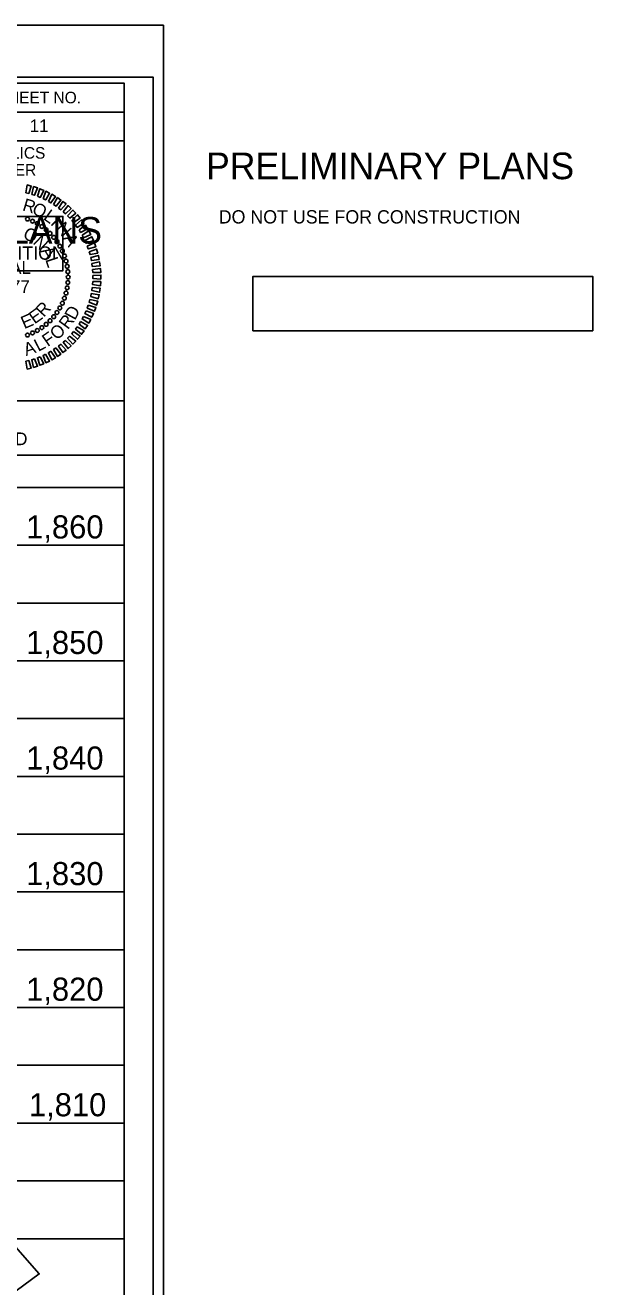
# Model space of a CAD drawing. Extents: x 557032 to 562069, y 513430 to 515874.
# Drawn here: x 558657 to 558902, y 515328 to 515874 of the extents above; entities that cross this region are included whole.
import ezdxf

# ---------------------------------------------------------------- set-up
doc = ezdxf.new("R2010")
doc.units = 0
for name, color, linetype in [('Default', 7, 'Continuous'), ('Exist Vertical Profile Vertical Axis Label', 7, 'Continuous'), ('Scratch_Level_5', 7, 'Continuous'), ('Sheet Cutting Line CELL', 7, 'Continuous'), ('Sheet Data Field CELL', 7, 'Continuous'), ('Sheet DOT Grid CELL', 7, 'Continuous'), ('Sheet Plot Border Inside CELL', 7, 'Continuous'), ('Sheet Plot Border Outside CELL', 7, 'Continuous'), ('Sheet Profile CELL', 7, 'Continuous'), ('Sheet Profile Grid Major CELL', 7, 'Continuous'), ('Sheet Profile Grid Middle CELL', 7, 'Continuous'), ('Sheet Sticker Exception Certification CELL', 7, 'Continuous'), ('Sheet Sticker Incomplete CELL', 7, 'Continuous'), ('Sheet Sticker Preliminary CELL', 7, 'Continuous')]:
    doc.layers.add(name, color=color, linetype=linetype)

msp = doc.modelspace()

# ---------------------------------------------------------------- linework, layer by layer
at = {"layer": 'Default'}
for points in [[(558656.99, 515801.79), (558657.57, 515805.17), (558659.28, 515804.71), (558658.21, 515801.49)], [(558659.51, 515801.11), (558660.32, 515804.45), (558662, 515803.87), (558660.71, 515800.73)], [(558661.98, 515800.26), (558663.02, 515803.53), (558664.66, 515802.83), (558663.15, 515799.79)], [(558664.38, 515799.23), (558665.65, 515802.43), (558667.24, 515801.62), (558665.52, 515798.69)], [(558666.71, 515798.05), (558668.2, 515801.14), (558669.72, 515800.23), (558667.8, 515797.42)], [(558668.95, 515796.7), (558670.65, 515799.68), (558672.1, 515798.66), (558669.99, 515796)], [(558671.09, 515795.2), (558672.99, 515798.06), (558674.37, 515796.94), (558672.08, 515794.43)], [(558673.11, 515793.55), (558675.21, 515796.27), (558676.51, 515795.06), (558674.05, 515792.72)], [(558675.02, 515791.77), (558677.31, 515794.34), (558678.52, 515793.04), (558675.9, 515790.87)], [(558676.8, 515789.86), (558679.26, 515792.26), (558680.38, 515790.88), (558677.62, 515788.9)], [(558678.44, 515787.83), (558681.06, 515790.05), (558682.08, 515788.59), (558679.19, 515786.82)], [(558679.94, 515785.69), (558682.71, 515787.72), (558683.62, 515786.2), (558680.61, 515784.62)], [(558681.28, 515783.45), (558684.19, 515785.29), (558684.99, 515783.7), (558681.88, 515782.34)], [(558682.47, 515781.12), (558685.49, 515782.75), (558686.18, 515781.11), (558682.99, 515779.97)], [(558683.49, 515778.71), (558686.62, 515780.13), (558687.19, 515778.45), (558683.92, 515777.53)], [(558684.33, 515776.24), (558687.55, 515777.44), (558688.01, 515775.72), (558684.69, 515775.04)], [(558685.01, 515773.72), (558688.3, 515774.69), (558688.64, 515772.94), (558685.28, 515772.49)], [(558685.5, 515771.16), (558688.86, 515771.89), (558689.08, 515770.12), (558685.69, 515769.91)], [(558685.82, 515768.56), (558689.22, 515769.06), (558689.31, 515767.28), (558685.91, 515767.31)], [(558685.91, 515763.34), (558689.34, 515763.36), (558689.19, 515761.59), (558685.83, 515762.09)], [(558685.95, 515765.95), (558689.38, 515766.21), (558689.35, 515764.44), (558685.96, 515764.7)], [(558685.26, 515758.16), (558688.67, 515757.7), (558688.27, 515755.97), (558685.01, 515756.93)], [(558685.68, 515760.74), (558689.1, 515760.52), (558688.82, 515758.77), (558685.51, 515759.5)], [(558683.91, 515753.12), (558687.22, 515752.19), (558686.58, 515750.53), (558683.49, 515751.94)], [(558684.68, 515755.62), (558688.04, 515754.92), (558687.52, 515753.22), (558684.34, 515754.41)], [(558681.87, 515748.32), (558685.01, 515746.94), (558684.15, 515745.38), (558681.28, 515747.2)], [(558682.97, 515750.68), (558686.21, 515749.53), (558685.45, 515747.92), (558682.47, 515749.53)], [(558677.6, 515741.76), (558680.39, 515739.76), (558679.22, 515738.42), (558676.8, 515740.79)], [(558679.17, 515743.84), (558682.1, 515742.04), (558681.03, 515740.62), (558678.44, 515742.82)], [(558680.6, 515746.03), (558683.64, 515744.44), (558682.67, 515742.95), (558679.94, 515744.96)], [(558672.06, 515736.23), (558674.38, 515733.69), (558672.95, 515732.62), (558671.08, 515735.45)], [(558674.04, 515737.95), (558676.52, 515735.57), (558675.18, 515734.41), (558673.11, 515737.1)], [(558675.88, 515739.79), (558678.53, 515737.6), (558677.27, 515736.34), (558675.02, 515738.88)], [(558663.13, 515730.88), (558664.65, 515727.8), (558662.99, 515727.16), (558661.97, 515730.4)], [(558665.5, 515731.98), (558667.23, 515729.01), (558665.62, 515728.26), (558664.37, 515731.42)], [(558667.78, 515733.24), (558669.72, 515730.41), (558668.16, 515729.54), (558666.7, 515732.61)], [(558669.98, 515734.66), (558672.11, 515731.97), (558670.61, 515731), (558668.94, 515733.95)], [(558658.19, 515729.18), (558659.27, 515725.92), (558657.54, 515725.52), (558656.97, 515728.87)], [(558660.69, 515729.94), (558662, 515726.77), (558660.29, 515726.25), (558659.5, 515729.55)]]:
    msp.add_lwpolyline(points, close=True, dxfattribs=at)
for centre in [(558657.67, 515790.42), (558659.83, 515789.53), (558661.89, 515788.45), (558663.86, 515787.2), (558665.7, 515785.78), (558667.42, 515784.21), (558668.99, 515782.49), (558670.41, 515780.64), (558671.66, 515778.68), (558672.74, 515776.61), (558673.63, 515774.46), (558674.33, 515772.24), (558674.83, 515769.97), (558675.13, 515767.66), (558675.13, 515763), (558675.24, 515765.33), (558674.32, 515758.42), (558674.83, 515760.69), (558671.66, 515751.98), (558672.73, 515754.05), (558673.62, 515756.2), (558667.41, 515746.45), (558668.99, 515748.17), (558670.4, 515750.02), (558659.82, 515741.14), (558661.88, 515742.21), (558663.85, 515743.46), (558665.7, 515744.88), (558657.67, 515740.25)]:
    msp.add_circle(centre, 0.826, dxfattribs=at)
at = {"layer": 'Scratch_Level_5'}
msp.add_lwpolyline([(558499.4, 515824.23), (557249.45, 515849.28), (557249.45, 515349.28), (557236.61, 515332.67), (557249.45, 515324.28), (558649.45, 515324.28), (558662.72, 515334.01), (558649.45, 515349.28), (558649.45, 515688.23), (558499.4, 515688.23)], close=True, dxfattribs=at)
at = {"layer": 'Sheet Cutting Line CELL'}
msp.add_line((558716.45, 515874.28), (557032.45, 515874.28), dxfattribs=at)
at = {"layer": 'Sheet DOT Grid CELL'}
for p, q in [((558699.45, 515649.28), (557199.45, 515649.28)), ((558699.45, 515599.28), (557199.45, 515599.28)), ((558699.45, 515549.28), (557199.45, 515549.28)), ((558699.45, 515499.28), (557199.45, 515499.28)), ((558699.45, 515449.28), (557199.45, 515449.28)), ((558699.45, 515399.28), (557199.45, 515399.28))]:
    msp.add_line(p, q, dxfattribs=at)
at = {"layer": 'Sheet Plot Border Inside CELL'}
msp.add_lwpolyline([(557045.45, 514796.73), (558711.95, 514796.73), (558711.95, 515851.83), (557045.45, 515851.83)], close=True, dxfattribs=at)
at = {"layer": 'Sheet Plot Border Outside CELL'}
msp.add_lwpolyline([(557032.45, 514774.28), (558716.45, 514774.28), (558716.45, 515874.28), (557032.45, 515874.28)], close=True, dxfattribs=at)
at = {"layer": 'Sheet Profile CELL'}
for p, q in [((558499.4, 515836.73), (558699.45, 515836.73)), ((557199.45, 515349.28), (558699.45, 515349.28))]:
    msp.add_line(p, q, dxfattribs=at)
for points in [[(558699.45, 515849.28), (557199.45, 515849.28), (557199.45, 514799.28), (558699.45, 514799.28)], [(558499.4, 515849.28), (558699.45, 515849.28), (558699.45, 515824.23), (558499.4, 515824.23)], [(558599.45, 515824.23), (558699.45, 515824.23), (558699.45, 515711.73), (558599.45, 515711.73)]]:
    msp.add_lwpolyline(points, close=True, dxfattribs=at)
at = {"layer": 'Sheet Profile Grid Major CELL'}
for points in [[(558649.45, 515688.23), (558649.45, 515349.28), (558699.45, 515349.28), (558699.45, 515699.28)], [(558699.45, 515649.28), (557199.45, 515649.28), (557199.45, 515599.28), (558699.45, 515599.28)], [(558699.45, 515549.28), (557199.45, 515549.28), (557199.45, 515499.28), (558699.45, 515499.28)], [(558699.45, 515449.28), (557199.45, 515449.28), (557199.45, 515449.28), (557199.45, 515399.28), (558699.45, 515399.28)]]:
    msp.add_lwpolyline(points, dxfattribs=at)
at = {"layer": 'Sheet Profile Grid Middle CELL'}
for points in [[(558699.45, 515674.28), (557199.45, 515674.28), (557199.45, 515624.28), (558524.45, 515624.28)], [(558524.45, 515624.28), (558699.45, 515624.28)], [(558699.45, 515574.28), (557199.45, 515574.28), (557199.45, 515524.28), (558699.45, 515524.28)], [(558699.45, 515474.28), (557199.45, 515474.28), (557199.45, 515424.28), (558699.45, 515424.28)], [(558699.45, 515374.28), (557199.45, 515374.28)]]:
    msp.add_lwpolyline(points, dxfattribs=at)
at = {"layer": 'Sheet Sticker Exception Certification CELL'}
for p, q in [((558499.4, 515711.73), (558699.44, 515711.73)), ((558499.4, 515711.73), (558699.44, 515711.73)), ((558699.44, 515711.72), (558699.44, 515688.22)), ((558699.44, 515711.72), (558699.44, 515688.22)), ((558699.44, 515688.23), (558499.4, 515688.23)), ((558699.44, 515688.23), (558499.4, 515688.23))]:
    msp.add_line(p, q, dxfattribs=at)
at = {"layer": 'Sheet Sticker Incomplete CELL'}
msp.add_lwpolyline([(558525.97, 515768.08), (558525.97, 515791.58), (558672.97, 515791.58), (558672.97, 515768.08)], close=True, dxfattribs=at)
at = {"layer": 'Sheet Sticker Preliminary CELL'}
msp.add_lwpolyline([(558755.17, 515742.13), (558755.17, 515765.63), (558902.17, 515765.63), (558902.17, 515742.13)], close=True, dxfattribs=at)

# ---------------------------------------------------------------- texts
at = {"layer": 'Default'}
for s, height, rotation, p in [('R', 5.5, 343.3983, (558655.15, 515794.24)), ('O', 5.5, 335.1897, (558659.21, 515793)), ('L', 5.5, 324.4645, (558664.17, 515790.53)), ('I', 5.5, 316.9994, (558667.31, 515788.29)), ('O', 5.5, 332.5394, (558655.27, 515782.46)), ('N', 5.5, 311.0594, (558669.58, 515786.22)), ('N', 5.5, 316.7306, (558659.68, 515779.98)), ('A', 5.5, 300.849, (558672.95, 515782.16)), ('A', 5.5, 301.6806, (558663.1, 515776.59)), ('L', 5.5, 288.3447, (558665.3, 515772.92)), ('SEAL', 5.504, 359.989, (558640.31, 515766.71)), ('31977', 5.504, 359.989, (558638.19, 515758.46)), ('R', 5.5, 47.032, (558664.65, 515747.7)), ('D', 5.5, 61.6895, (558678.17, 515746.35)), ('E', 5.5, 23.5075, (558656.27, 515742.74)), ('E', 5.5, 35.2697, (558660.71, 515744.79)), ('R', 5.5, 53.4809, (558675.15, 515742.31)), ('F', 5.5, 34.833, (558666.39, 515735.01)), ('O', 5.5, 42.7557, (558670.4, 515737.76)), ('A', 5.5, 18.3204, (558657.04, 515731.18)), ('L', 5.5, 27.3679, (558662.3, 515732.95))]:
    msp.add_text(s, height=height, rotation=rotation, dxfattribs=at).set_placement(p)
at = {"layer": 'Exist Vertical Profile Vertical Axis Label'}
for s, p in [('1,860', (558657.07, 515652.23)), ('1,860', (558657.07, 515652.23)), ('1,860', (558657.07, 515652.23)), ('1,860', (558657.07, 515652.23)), ('1,850', (558657.07, 515602.23)), ('1,850', (558657.07, 515602.23)), ('1,850', (558657.07, 515602.23)), ('1,850', (558657.07, 515602.23)), ('1,840', (558657.07, 515552.23)), ('1,840', (558657.07, 515552.23)), ('1,840', (558657.07, 515552.23)), ('1,840', (558657.07, 515552.23)), ('1,830', (558657.07, 515502.23)), ('1,830', (558657.07, 515502.23)), ('1,830', (558657.07, 515502.23)), ('1,830', (558657.07, 515502.23)), ('1,820', (558657.07, 515452.23)), ('1,820', (558657.07, 515452.23)), ('1,820', (558657.07, 515452.23)), ('1,820', (558657.07, 515452.23)), ('1,810', (558658.27, 515402.23)), ('1,810', (558658.27, 515402.23)), ('1,810', (558658.27, 515402.23)), ('1,810', (558658.27, 515402.23))]:
    msp.add_text(s, height=10, dxfattribs=at).set_placement(p)
at = {"layer": 'Sheet Data Field CELL'}
msp.add_text('11 ', height=5.5, dxfattribs=at).set_placement((558658.59, 515828.02))
at = {"layer": 'Sheet Profile CELL'}
for s, p in [('SHEET NO.', (558644.77, 515840.5)), ('HYDRAULICS', (558622.27, 515816.55)), ('ENGINEER', (558626.52, 515809.2))]:
    msp.add_text(s, height=5, dxfattribs=at).set_placement(p)
at = {"layer": 'Sheet Sticker Exception Certification CELL'}
msp.add_text('UNLESS ALL SIGNATURES COMPLETED', height=5.5, dxfattribs=at).set_placement((558515.4, 515692.59))
msp.add_text('UNLESS ALL SIGNATURES COMPLETED', height=5.5, dxfattribs=at).set_placement((558515.4, 515692.59))
at = {"layer": 'Sheet Sticker Incomplete CELL'}
for s, height, p in [('INCOMPLETE PLANS', 11.52, (558534.93, 515779.78)), ('DO NOT USE FOR R/W ACQUISITION', 5.76, (558538.18, 515772.83))]:
    msp.add_text(s, height=height, dxfattribs=at).set_placement(p)
at = {"layer": 'Sheet Sticker Preliminary CELL'}
for s, height, p in [('PRELIMINARY PLANS', 11.52, (558734.88, 515807.67)), ('DO NOT USE FOR CONSTRUCTION', 5.76, (558740.37, 515788.5))]:
    msp.add_text(s, height=height, dxfattribs=at).set_placement(p)

doc.saveas('drawing.dxf')
